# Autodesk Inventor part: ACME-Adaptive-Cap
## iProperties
Company: Autodesk, Inc.
Shininess: 64.0
Length Units: 11269
Angle Units: 11279
Time Units: 11290
Mass Units: 11283
Length Display Precision: 3
Angle Display Precision: 2
Compacted: True
Part Number: ACME-Adaptive-Cap
Document SubType Name: Modeling
Created: 2003-12
Catalog Web Link: www.autodesk.com
Vendor: Autodesk, Inc.
Designer: Administrator
Manufacturer: Standard
Standards Organization: Custom
Density: 1 g/cm^3
Mass: 1.70592 g
Surface Area: 16.9925 cm^2
Volume: 1.70592 cm^3
Density: 0.0
Volumn: 0.0
Area: 0.0
PropertySet Name: Model Information
Control State: 0
Master: False
Checked Out: False
Author: Administrator
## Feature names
1. Extrusion1
